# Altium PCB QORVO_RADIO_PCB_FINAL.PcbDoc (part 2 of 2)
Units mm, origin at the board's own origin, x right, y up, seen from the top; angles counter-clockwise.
Board outline 125 x 75 mm, 6 copper layers (Top Layer (RF), Int1 (GND), Int2 (5V+3.3V), Int3 (Controls), Int4 (GND), Bottom Layer (RF)), stack 1.538 mm thick; 307 components, 160 nets, 820 pads, 887 vias.
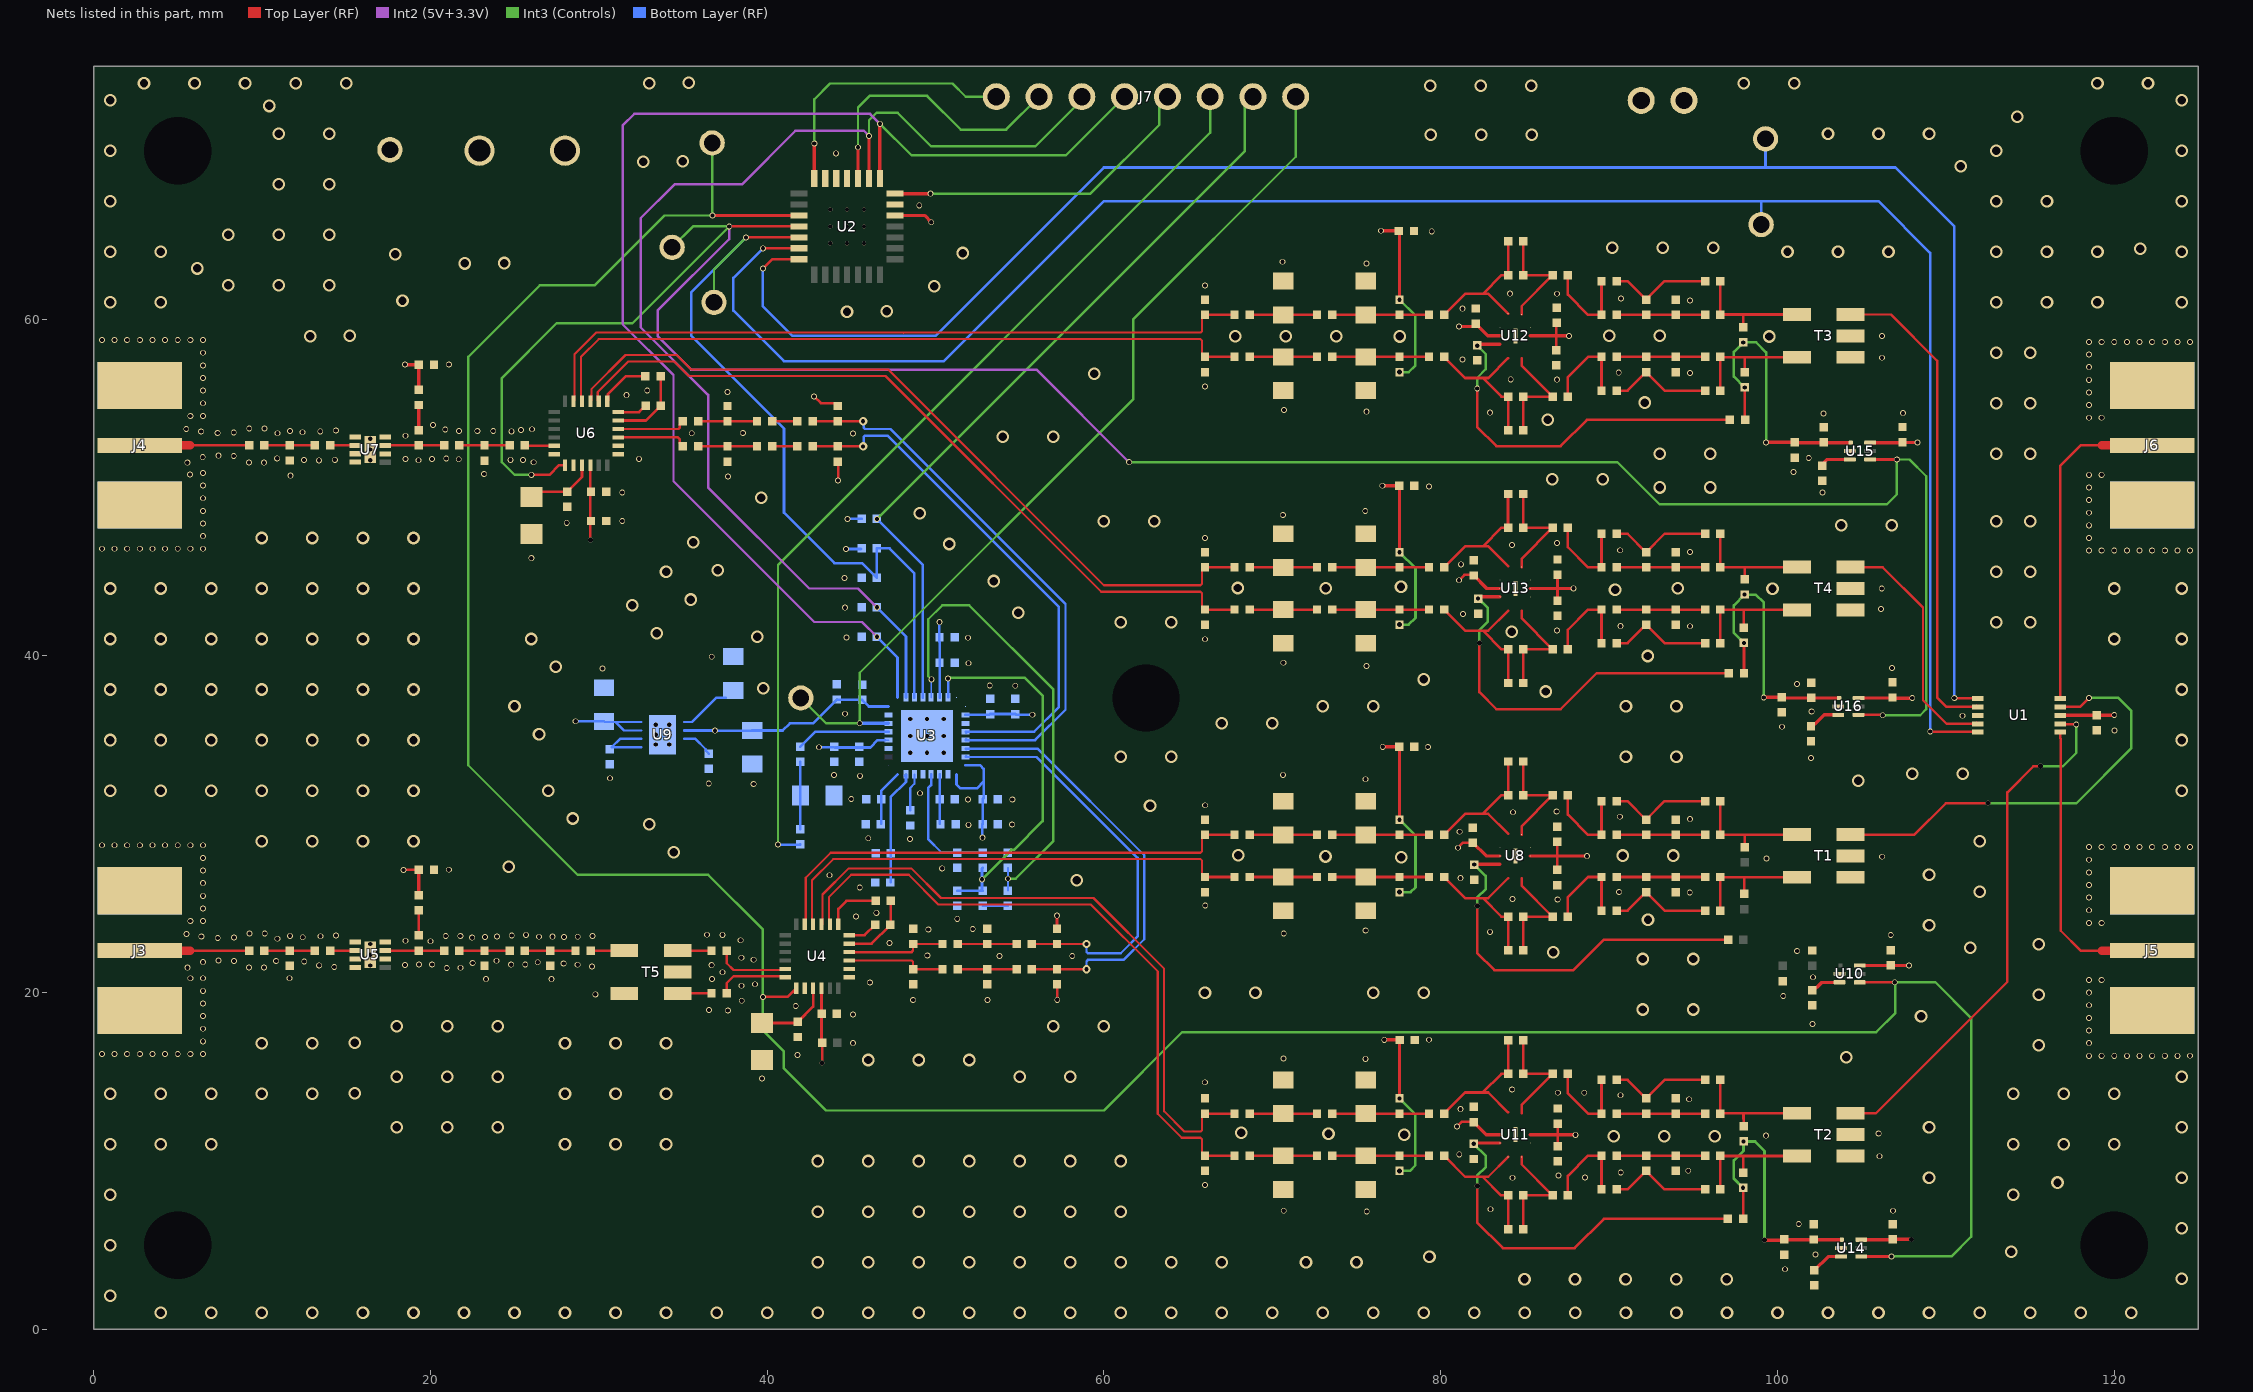
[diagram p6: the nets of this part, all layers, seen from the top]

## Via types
v1: diameter 0.35, hole 0.25, Top Layer (RF) to Bottom Layer (RF), 474 vias
v2: diameter 0.75, hole 0.5, Top Layer (RF) to Bottom Layer (RF), 365 vias
v3: diameter 0.254, hole 0.254, Top Layer (RF) to Bottom Layer (RF), tented bottom, 15 vias
v4: diameter 0.3, hole 0.3, Top Layer (RF) to Bottom Layer (RF), 14 vias
v5: diameter 0.254, hole 0.254, Top Layer (RF) to Bottom Layer (RF), tented top, 9 vias
v6: diameter 0.254, hole 0.254, Top Layer (RF) to Bottom Layer (RF), 4 vias
v7: diameter 0.5, hole 0.25, Top Layer (RF) to Bottom Layer (RF), 4 vias
v8: diameter 0.254/0.254/0.254/0.254/0.254/0.254 (per signal layer), hole 0.254, Top Layer (RF) to Bottom Layer (RF), tented top, 2 vias

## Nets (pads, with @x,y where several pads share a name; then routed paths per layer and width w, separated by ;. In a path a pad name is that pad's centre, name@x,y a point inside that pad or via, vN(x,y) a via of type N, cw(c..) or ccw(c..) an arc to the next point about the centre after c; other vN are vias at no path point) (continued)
"0.9V REG OUT_2": C118.2 C139.1 R50.2 R51.2 R56.2 U14.1 | length 16.3
  Top Layer (RF) w0.152: R56.2@97.958,6.57 R50.2@97.958,8.4
  Top Layer (RF) w0.156: C118.2@100.375,5.308 C118.2@100.411,5.344
  Top Layer (RF) w0.2: v4(99.23,5.308) C118.2@100.375,5.308 ; C118.2@100.563,5.33 U14.1@103.823,5.33
  Int3 (Controls) w0.156: v1(97.949,8.409) 97.409,8.949 97.409,10.033 97.98,10.604 v1(97.98,11.159) 98.67,11.159 99.23,10.599 v4(99.23,5.308)
"0.9V REG OUT_3": C127.2 C142.1 R63.2 R64.2 R69.2 U15.1 | length 17
  Top Layer (RF) w0.152: R69.2@98.053,54.041 v1(98.053,55.942)
  Top Layer (RF) w0.2: v1(99.323,52.676) 99.324,52.675 101.019,52.675 C127.2@101.02,52.676 ; C127.2@101.035,52.662 102.75,52.662 U15.1@104.351,52.662
  Int3 (Controls) w0.15: v1(98.053,55.942) 97.409,56.586 97.409,58.052 v1(97.971,58.614) 98.739,58.614 99.33,58.023 v1@99.33,52.683
"0.9V REG OUT_4": C136.2 C145.1 R76.2 R77.2 R82.2 U16.1 | length 16.6
  Top Layer (RF) w0.152: R82.2@98.01,38.968 v1(98.011,40.764)
  Top Layer (RF) w0.156: R82.2@98.01,38.968 R82.2@98.01,38.968
  Top Layer (RF) w0.2: v1@99.196,37.542 C136.2@100.259,37.542 ; C136.2@100.305,37.495 U16.1@103.663,37.495
  Int3 (Controls) w0.156: v1(98.011,40.764) 97.409,41.366 97.409,42.999 v1(98.048,43.638) 98.704,43.638 99.185,43.156 v1(99.185,37.531)
AVDD: C13.2 C14.2 C15.2 C16.2 C23.2 C24.2 C25.2 C26.2 C39.2 C40.2 C85.2 R9.2 R10.2 R83.2 R84.2 R85.2 R86.2 U3.6 U3.10 U3.16 U3.17 U3.28 U3.32 U9.2 | length 39.5
  Top Layer (RF) w0.156: v1(42.79,55.408) 43.189,55.009 44.028,55.009 R85.2@44.2,54.837 ; v1(44.217,50.413) R86.2@44.217,51.521 ; R83.2@57.213,23.793 v1(57.213,24.571) ; v1(57.231,19.574) R84.2@57.231,20.475
  Bottom Layer (RF) w0.1: U3.28@47.009,34.994 U3.28@47.209,34.994
  Bottom Layer (RF) w0.156: U9.2@35.07,35.57 v1@36.889,35.57 ; v1(36.903,35.556) 39.106,35.556 C85.2@39.12,35.569 40.929,35.569 41.351,35.992 42.732,35.992 C16.2@44.148,37.407 ; v1(43.082,34.569) C13.2@43.939,34.569 ; C13.2@44.03,34.558 46.13,34.558 46.566,34.994 U3.28@47.009,34.994 ; C16.2@44.169,37.386 C15.2@45.648,37.386 46.04,36.994 U3.32@47.209,36.994 ; v1(44.693,46.342) R10.2@45.58,46.342 ; v1(44.782,48.134) R9.2@45.614,48.134 ; 50.231,40.838 v1(50.231,41.999) ; U3.6@50.245,37.53 50.245,40.838 ; U3.17@51.245,32.958 51.245,32.367 51.467,32.145 52.483,32.145 52.864,32.526 ; U3.16@51.781,33.494 52.658,33.494 52.864,33.288 52.864,32.526 ; U3.10@51.781,36.494 C40.2@53.195,36.494 ; v1(52.784,29.203) C26.2@52.784,29.982 ; C26.2@52.795,29.993 C25.2@52.795,31.493 52.864,31.562 52.864,32.526 ; C40.2@53.245,36.544 C39.2@54.745,36.544 ; C39.2@54.789,36.5 v1(55.75,36.5)
CHIP_EN: J7.7 R9.1 U3.4 | length 46.1
  Int3 (Controls) w0.142: v1@46.574,48.13 v1(46.518,48.13) 68.372,69.985 68.372,72.727 J7.7@68.85,73.205
  Bottom Layer (RF) w0.156: v1(46.518,48.13) 49.245,45.403 U3.4@49.245,37.53
CPOUT: C10.2 C12.1 R5.1 U3.7 | length 22.5
  Int3 (Controls) w0.142: v1(50.737,38.653) 50.777,38.692 55.308,38.692 56.361,37.639 56.361,30.185 54.652,28.476 54.509,28.476 v1(52.761,26.728)
  Bottom Layer (RF) w0.15: U3.7@50.745,37.53 v1@50.745,38.645 ; C10.2@51.295,26.056 52.056,26.056 ; 52.089,26.056 C12.1@52.795,26.056 52.761,26.09 v1(52.761,26.728) 52.761,27.371 R5.1@52.795,27.406
CS: J7.5 U2.7 | length 19.2
  Top Layer (RF) w0.2: U2.7@47.6,67.45 v1@49.7,67.45
  Int3 (Controls) w0.142: v1(49.705,67.446) 59.196,67.446 63.292,71.542 63.292,72.727 J7.5@63.77,73.205
GND: C1.1 C2.2 C3.2 C4.2 C5.1 C6.1 C7.1 C10.1 C11.1 C13.1 C14.1 C15.1 C16.1 C17.2 C18.2 C19.2 C20.2 C21.2 C22.2 C23.1 C24.1 C25.1 C26.1 C27.2 C29.2 C34.1 C38.1 C39.1 C40.1 C49.1 C50.1 C52.2 C55.1 C57.1 C67.1 C68.1 C69.1 C70.2 C73.1 C75.2 C76.2 C77.1 C78.1 C79.1 C80.1 C82.1 C83.2 C84.2 C85.1 C86.1 C87.1 C88.2 C89.2 C90.1 C91.1 C92.2 C93.2 C94.2 C95.1 C96.1 C97.1 C98.1 C99.2 C100.2 C101.2 C102.1 C103.1 C104.1 C105.1 C106.2 C107.2 C108.2 C109.1 C110.1 C111.1 C113.2 C114.2 C115.1 C116.1 C117.1 C118.1 C120.1 C122.2 C123.2 C124.1 C125.1 C126.1 C127.1 C129.1 C131.2 C132.2 C133.1 C134.1 C135.1 C136.1 C138.1 C139.2 C140.2 C141.1 C142.2 C143.2 C144.1 C145.2 C146.2 C147.1 C148.2 C149.2 C150.1 J1.2 J2.1 J2.2 J3.1 J3.3 J3.4 J3.5 J4.1 J4.3 J4.4 J4.5 J5.1 J5.3 J5.4 J5.5 J6.1 J6.3 J6.4 J6.5 R6.2 R8.2 R11.2 R12.1 R13.1 R14.1 R15.1 R16.1 R17.1 R18.1 T1.2 T1.3 T2.2 T2.3 T3.2 T3.3 T4.2 T4.3 T5.2 T5.4 U1.3 U2.6 U2.11 U2.12 U2.13 U2.29 U3.8 U3.9 U3.11 U3.18 U3.21 U3.27 U3.31 U3.33 U4.8 U4.13 U4.14 U4.25 U5.1 U5.3 U5.4 U5.6 U5.8 U5.9 U6.6 U6.8 U6.13 U6.14 U6.25 U7.1 U7.3 U7.4 U7.6 U7.8 U7.9 U8.8 U8.10 U8.11 U9.4 U9.9 U10.2 U11.8 U11.10 U11.11 U12.8 U12.10 U12.11 U13.8 U13.10 U13.11 U14.2 U15.2 U16.2
  other v1: 100.45,3.572 102.254,4.446 101.265,6.263 75.609,6.999 70.679,7.047 106.854,7.046 82.954,7.139 66.007,8.583 84.261,9.008 88.569,9.021 86.995,9.136 90.69,9.316 94.698,9.423 106.057,10.284 81.1,10.4 99.324,11.508 106.007,11.631 81.174,13.081 94.754,13.671 90.672,13.905 86.955,14.053 88.525,14.057 84.245,14.242 65.993,14.676 39.7,14.9 70.658,16.084 75.534,16.07 118.5,16.25 119.25,16.25 120,16.25 120.75,16.25 121.5,16.25 122.25,16.25 123,16.25 123.75,16.25 124.5,16.25 41.8,16.3 0.5,16.358 1.25,16.358 2,16.358 2.75,16.358 3.5,16.358 4.25,16.358 5,16.358 5.75,16.358 6.5,16.358 45.1,17 118.5,17 6.5,17.108 79.3,17.2 118.5,17.75 6.5,17.858 102.086,18.143 118.5,18.5 6.5,18.608 45.1,18.7 37.667,18.946 36.556,18.973 41.7,19.2 118.5,19.25 6.5,19.358 38.496,19.518 48.675,19.562 53.08,19.556 100.34,19.804 29.8,19.9 118.5,20 6.5,20.108 38.474,20.41 39.282,20.499 46.1,20.6 118.5,20.75 119.25,20.75 23.3,20.8 27.2,20.8 36.725,20.816 5.75,20.858 6.5,20.858 11.633,20.853 102.115,20.912 37.348,21.209 20.975,21.465 5.58,21.484 10.132,21.485 21.788,21.481 9.242,21.501 14.295,21.524 29.603,21.556 13.401,21.624 18.492,21.638 36.707,21.632 19.335,21.674 20.112,21.679 24.802,21.662 25.641,21.669 28.752,21.659 27.921,21.73 22.517,21.768 26.379,21.804 6.497,21.81 12.518,21.85 10.848,21.881 7.426,21.902 8.338,21.888 23.931,21.893 39.202,21.952 38.47,22.073 53.806,22.177 58.124,22.184 49.515,22.199 101.168,22.475 47.274,22.95 20.013,23.052 18.531,23.079 38.429,23.113 10.916,23.202 7.381,23.252 8.336,23.271 22.488,23.264 12.423,23.292 23.253,23.304 27.934,23.299 26.462,23.321 27.248,23.325 28.756,23.321 6.403,23.336 13.474,23.347 23.965,23.331 11.668,23.373 20.92,23.362 21.783,23.372 29.638,23.364 14.4,23.4 24.838,23.389 106.722,23.419 25.691,23.434 36.431,23.439 37.354,23.435 5.515,23.482 9.26,23.51 10.168,23.513 70.678,23.519 82.92,23.611 75.545,23.69 49.573,23.745 52.21,23.784 118.5,24.142 119.25,24.142 5.75,24.25 6.5,24.25 51.291,24.383 45.278,24.524 46.487,24.74 118.5,24.892 6.5,25 66.015,25.181 86.945,25.533 84.257,25.563 118.5,25.642 6.5,25.75 90.598,25.97 94.79,25.951 45.5,26.25 118.5,26.392 6.5,26.5 81.183,26.797 43.709,26.969 118.5,27.142 6.5,27.25 21.1,27.3 50.395,27.383 118.5,27.892 99.34,27.973 6.5,28 106.217,28.068 118.5,28.642 119.25,28.642 120,28.642 120.75,28.642 121.5,28.642 122.25,28.642 123,28.642 123.75,28.642 124.5,28.642 0.5,28.75 1.25,28.75 2,28.75 2.75,28.75 3.5,28.75 4.25,28.75 5,28.75 5.75,28.75 6.5,28.75 48.492,29.121 46.009,29.166 81.126,29.554 51.958,29.966 54.552,29.978 94.806,30.303 90.638,30.443 84.286,30.715 86.888,30.752 66.013,31.126 51.938,31.467 54.563,31.475 45,31.5 49.087,31.843 39.204,32.395 36.537,32.422 75.534,32.672 30.676,32.734 45.519,32.876 43.97,32.929 70.638,32.936 101.991,33.937 79.234,34.596 120.019,35.561 100.269,35.79 110.983,36.444 44.628,36.559 102.029,36.696 53.22,38.234 54.735,38.226 101.166,38.334 30.228,39.243 106.795,39.286 75.598,39.393 51.957,39.56 70.656,39.593 36.715,39.948 66.008,40.984 51.933,41.075 44.715,41.09 86.9,41.5 90.674,41.762 94.803,41.759 81.318,42.485 106.148,42.781 44.632,42.861 106.189,43.995 44.589,44.626 81.207,45.436 26,45.8 94.803,46.172 118.5,46.25 119.25,46.25 120,46.25 120.75,46.25 121.5,46.25 122.25,46.25 123,46.25 123.75,46.25 124.5,46.25 90.657,46.272 0.5,46.358 1.25,46.358 2,46.358 2.75,46.358 3.5,46.358 4.25,46.358 5,46.358 5.75,46.358 6.5,46.358 84.23,46.582 86.9,46.7 66.002,46.998 118.5,47 6.5,47.108 118.5,47.75 6.5,47.858 28.1,47.9 31.4,48 70.625,48.358 118.5,48.5 6.5,48.608 75.516,48.608 118.5,49.25 6.5,49.358 31.4,49.7 102.68,49.702 118.5,50 79.31,50.049 6.5,50.108 37.671,50.656 11.7,50.7 118.5,50.75 119.25,50.75 5.728,50.769 23.2,50.8 6.5,50.858 100.955,50.911 5.572,51.471 10.123,51.471 9.233,51.488 26.14,51.497 13.392,51.61 19.303,51.615 12.505,51.628 14.33,51.64 24.766,51.641 25.508,51.636 21.691,51.671 18.524,51.684 20.109,51.693 32.4,51.7 20.949,51.723 10.907,51.73 101.856,51.742 6.488,51.797 8.329,51.874 7.417,51.888 18.532,53.067 10.921,53.215 35.522,53.215 45.102,53.211 7.372,53.239 38.558,53.23 8.327,53.257 12.415,53.279 6.395,53.322 11.664,53.353 13.465,53.333 21.703,53.352 24.819,53.331 22.794,53.361 23.737,53.356 14.391,53.386 25.379,53.404 20.885,53.438 5.507,53.469 26.043,53.455 9.252,53.496 10.16,53.499 20.165,53.705 118.5,54.142 119.25,54.142 5.75,54.25 6.5,54.25 102.738,54.386 107.455,54.411 82.936,54.44 75.6,54.5 70.7,54.6 118.5,54.892 6.5,55 31.645,55.479 118.5,55.642 37.657,55.673 6.5,55.75 32.885,55.753 66,56 86.9,56.4 118.5,56.392 84.157,56.42 6.5,56.5 94.8,56.8 90.575,56.817 118.5,57.142 6.5,57.25 21.1,57.3 81.3,57.6 106.2,57.7 118.5,57.892 6.5,58 118.5,58.642 119.25,58.642 120,58.642 120.75,58.642 121.5,58.642 122.25,58.642 123,58.642 123.75,58.642 124.5,58.642 0.5,58.75 1.25,58.75 2,58.75 2.75,58.75 3.5,58.75 4.25,58.75 5,58.75 5.75,58.75 6.5,58.75 106.2,59 81.301,60.616 94.8,61.1 90.701,61.221 86.9,61.5 84.115,61.506 66,62 75.6,63.3 70.6,63.4 79.471,65.209 49.037,66.753 44.095,69.842
  other v2: 4,1 7,1 10,1 13,1 16,1 19,1 22,1 25,1 28,1 31,1 34,1 37,1 40,1 43,1 46,1 49,1 52,1 55,1 58,1 61,1 64,1 67,1 70,1 73,1 76,1 79,1 82,1 85,1 88,1 91,1 94,1 97,1 100,1 103,1 106,1 109,1 112,1 115,1 118,1 121,1 1,2 84.977,2.977 87.977,2.977 90.977,2.977 93.977,2.977 96.977,2.977 124,3 43,4 46,4 49,4 52,4 55,4 58,4 61,4 64,4 67,4 72,4 75,4 79.332,4.315 113.887,4.61 1,5 124,6 43,7 46,7 49,7 52,7 55,7 58,7 61,7 1,8 114,8 116.629,8.723 109,9 124,9 43,10 46,10 49,10 52,10 55,10 58,10 61,10 1,11 4,11 7,11 28,11 31,11 34,11 114,11 117,11 120,11 90.267,11.468 93.267,11.468 96.267,11.468 77.838,11.558 73.34,11.614 68.159,11.683 18,12 21,12 24,12 109,12 124,12 1,14 4,14 7,14 10,14 13,14 28,14 31,14 34,14 114,14 117,14 120,14 15.517,14.023 18,15 21,15 24,15 55,15 58,15 124,15 46,16 49,16 52,16 104.089,16.165 115.524,16.884 10,17 13,17 28,17 31,17 34,17 15.517,17.023 18,18 21,18 24,18 57,18 60,18 108.524,18.605 92,19 95,19 115.524,19.884 66,20 69,20 76,20 79,20 92,22 95,22 86.683,22.395 111.454,22.658 115.524,22.884 109,24 92.311,24.325 112,26 58.397,26.681 109,27 24.657,27.468 77.658,28.031 73.16,28.088 67.979,28.156 90.808,28.141 93.808,28.141 34.457,28.344 10,29 13,29 16,29 19,29 112,29 33,30 28.457,30.344 62.74,31.109 1,32 4,32 7,32 10,32 13,32 16,32 19,32 27,32 124,32 104.788,32.589 108,33 111,33 61,34 64,34 91,34 94,34 1,35 4,35 7,35 10,35 13,35 16,35 19,35 124,35 26.457,35.344 67,36 70,36 25,37 73,37 76,37 91,37 94,37 86.237,37.884 1,38 4,38 7,38 10,38 13,38 16,38 19,38 124,38 39.762,38.066 79,38.599 27.457,39.344 92.295,39.989 1,41 4,41 7,41 10,41 13,41 16,41 19,41 26,41 120,41 124,41 39.42,41.128 33.457,41.344 84.216,41.433 61,42 64,42 113,42 115,42 54.91,42.569 32,43 35.457,43.344 90.353,43.931 99.702,43.979 1,44 4,44 7,44 10,44 13,44 16,44 19,44 120,44 124,44 67.941,44.029 73.183,44.013 94.075,44.013 77.644,44.111 53.451,44.442 34,45 113,45 115,45 37.063,45.093 50.821,46.64 35.605,46.749 10,47 13,47 16,47 19,47 103.783,47.756 106.783,47.756 60,48 63,48 113,48 115,48 49.056,48.477 39.654,49.395 93,50 96,50 86.627,50.481 89.627,50.481 93,52 96,52 113,52 115,52 54,53 57,53 86.35,54.021 113,55 115,55 92.118,55.042 59.427,56.75 113,58 115,58 99.501,58.962 12.871,58.987 67.808,58.989 70.808,58.989 73.808,58.989 77.575,58.967 15.227,59.009 90,59 93,59 44.747,60.435 47.103,60.458 1,61 4,61 113,61 116,61 119,61 124,61 18.35,61.084 49.924,61.943 8,62 11,62 14,62 6.164,63.005 22.042,63.302 24.398,63.325 17.93,63.852 51.609,63.919 100.593,63.994 103.593,63.994 106.593,63.994 1,64 4,64 113,64 116,64 119,64 124,64 121.55,64.185 90.19,64.224 93.19,64.224 96.19,64.224 8,65 11,65 14,65 1,67 113,67 116,67 124,67 11,68 14,68 110.886,69.068 32.646,69.337 35.002,69.36 1,70 113,70 124,70 79.399,70.95 82.399,70.95 85.399,70.95 11,71 14,71 103,71 106,71 109,71 114.236,72.006 10.443,72.654 1,73 124,73 79.373,73.855 82.373,73.855 85.373,73.855 3,74 6,74 9,74 12,74 15,74 33,74 98,74 101,74 119,74 122,74 35.356,74.022
  other v3: 48.495,34.244 49.495,34.244 50.495,34.244 33.395,34.735 34.195,34.735 48.495,35.244 49.495,35.244 50.495,35.244 33.395,35.32 34.195,35.32 33.395,35.905 34.195,35.905 48.495,36.244 49.495,36.244 50.495,36.244
  other v5: 43.75,64.5 44.75,64.5 45.75,64.5 43.75,65.5 44.75,65.5 45.75,65.5 43.75,66.5 44.75,66.5 45.75,66.5
  other v6: 16.435,21.61 16.435,22.25 16.435,51.61 16.435,52.25
  other v8: 16.435,22.89 16.435,52.89
"HE LNA OUTPUT": C72.2 U6.5 | length 1.7
  Top Layer (RF) w0.143: C72.2@25.643,52.473 U6.5@27.355,52.473
"HEM EN": HEMEN.1 U2.18 U6.7 U15.4 U16.4 | length 144.6
  Top Layer (RF) w0.157: v1(26,50.75) 27.072,50.75 27.645,51.323 U6.7@28.005,51.323 ; v1(37.75,65.5) U2.18@41.9,65.5 ; U16.4@104.813,36.495 v1@106.23,36.495 ; U15.4@105.501,51.662 v1@107.082,51.662
  Int2 (5V+3.3V) w0.142: v1(37.75,65.5) 37.75,64.75 33.5,60.5 33.5,59 35.5,57 56,57 v1(61.5,51.5)
  Int3 (Controls) w0.142: v1(26,50.75) 25,50.75 24.25,51.5 24.25,56.5 27.5,59.75 32,59.75 v1(37.75,65.5) 35.602,65.5 HEMEN.1@34.361,64.259 ; v1(61.5,51.5) 90.5,51.5 93,49 106.5,49 107.085,49.585 v1(107.085,51.659) 107.841,51.659 108.835,50.665 108.835,36.835 108.475,36.475 v1(106.251,36.475)
"I HE CH": T3.1 U1.2 | length 29
  Top Layer (RF) w0.143: T3.1@104.34,60.27 106.73,60.27 109.476,57.524 109.476,37.524 110.034,36.966 U1.2@111.895,36.966 U1.2@111.817,37.044
"I LE CH": T1.1 U1.9 | length 25.8
  Top Layer (RF) w0.143: T1.1@104.34,29.388 108.138,29.388 110,31.25 v4(112.5,31.25) ; U1.9@116.795,36.966 117.966,36.966 v1(118.5,37.5)
  Int3 (Controls) w0.142: v4(112.5,31.25) 117.75,31.25 121,34.5 121,36.75 120.25,37.5 v1(118.5,37.5)
I/O_I: SWI.1 U1.1 U2.21 | length 112.8
  Top Layer (RF) w0.157: v1(39.75,63) 40.3,63.55 U2.21@41.9,63.55 ; v1@110.517,37.483 111.878,37.483 U1.1@111.895,37.466
  Bottom Layer (RF) w0.157: v1(39.75,63) 39.75,60.75 41.5,59 50,59 60,69 107,69 110.487,65.513 110.487,37.513 v1(110.5,37.5) ; 99.291,69.002 SWI.1@99.291,70.703
I/O_Q: SWQ.1 U1.5 U2.20 | length 116.7
  Top Layer (RF) w0.157: v1(39.75,64.2) U2.20@41.9,64.2 ; v1@109.09,35.487 111.874,35.487 U1.5@111.895,35.466
  Bottom Layer (RF) w0.157: v1(39.75,64.2) 38,62.45 38,60.5 41,57.5 50.5,57.5 60,67 106,67 109.068,63.932 v1(109.068,35.509) ; SWQ.1@99.033,65.608 99.033,66.967
I_HE_AA_N: L41.2 R60.2 R64.1 T3.6 | length 7.3
  Top Layer (RF) w0.152: L41.2@96.6,60.27 R60.2@96.6,62.25 ; L41.2@96.62,60.27 T3.6@101.16,60.27 ; R64.1@97.971,59.514 97.971,60.263
I_HE_AA_P: L43.2 R63.1 R67.2 T3.4 | length 7.4
  Top Layer (RF) w0.152: R67.2@96.6,55.75 L43.2@96.6,57.73 ; L43.2@96.62,57.73 T3.4@101.16,57.73 ; R63.1@98.044,56.838 98.044,57.727
I_HE_LPF_INPUT_N: C102.2 L30.1 U6.22 | length 42.8
  Top Layer (RF) w0.128: U6.22@28.946,55.182 28.946,57.755 30,58.809 47.942,58.809 65.742,58.809 65.819,58.731 C102.2@65.819,57.934
  Top Layer (RF) w0.133: U6.22@28.946,55.182 U6.22@29.005,55.123 ; C102.2@65.819,57.934 C102.2@66.003,57.75
  Top Layer (RF) w0.152: C102.2@66.003,57.75 L30.1@67.753,57.75
I_HE_LPF_INPUT_P: C99.1 L28.1 U6.23 | length 43.4
  Top Layer (RF) w0.128: 28.564,55.484 28.564,57.914 29.842,59.191 48.101,59.191 65.742,59.191 65.819,59.269 C99.1@65.819,60.066
  Top Layer (RF) w0.133: U6.23@28.505,55.123 28.564,55.182 28.564,55.484 ; C99.1@65.819,60.066 C99.1@66.003,60.25
  Top Layer (RF) w0.152: C99.1@66.003,60.25 L28.1@67.753,60.25
I_HE_LPF_OUTPUT_N: C128.1 R39.2 R68.1 U12.6 | length 8.8
  Top Layer (RF) w0.152: R39.2@80.203,57.75 81.453,56.5 82.5,56.5 ; C128.1@84,53.39 R68.1@84,55.39 83.61,55.39 82.5,56.5 ; U12.6@84,57.675 82.825,56.5 82.5,56.5
I_HE_LPF_OUTPUT_P: C121.1 R38.2 R57.1 U12.2 | length 8.8
  Top Layer (RF) w0.152: R38.2@80.203,60.25 81.453,61.5 82.825,61.5 U12.2@84,60.325 ; 82.5,61.5 83.61,62.61 R57.1@84,62.61 C121.1@84,64.61
I_LE_AA_N: L21.2 R22.2 R26.1 T1.6 | length 7.3
  Top Layer (RF) w0.152: L21.2@96.6,29.388 R22.2@96.6,31.368 ; L21.2@96.62,29.388 T1.6@101.16,29.388 ; R26.1@98.053,28.643 98.053,29.379
I_LE_AA_P: L23.2 R25.1 R29.2 T1.4 | length 7.5
  Top Layer (RF) w0.152: R29.2@96.6,24.868 L23.2@96.6,26.848 ; L23.2@96.62,26.848 T1.4@101.16,26.848 ; R25.1@98.021,25.863 98.021,26.825
I_LE_LPF_INPUT_N: C95.2 L26.1 U4.22 | length 29.1
  Top Layer (RF) w0.128: U4.22@42.731,24.059 42.67,24.12 42.67,26.67 43.929,27.929 60.441,27.929 65.742,27.929 65.817,27.854 65.817,27.054 C95.2@66.003,26.868
  Top Layer (RF) w0.152: C95.2@66.003,26.868 L26.1@67.753,26.868
I_LE_LPF_INPUT_P: C92.1 L24.1 U4.23 | length 29.9
  Top Layer (RF) w0.128: U4.23@42.231,24.059 42.292,24.059 42.292,26.826 43.773,28.307 60.597,28.307 65.742,28.307 65.817,28.382 65.817,29.182 C92.1@66.003,29.368
  Top Layer (RF) w0.15: U4.23@42.231,24.059 U4.23@42.281,24.109
  Top Layer (RF) w0.152: C92.1@66.003,29.368 L24.1@67.753,29.368
I_LE_LPF_OUTPUT_N: C81.1 R30.1 R35.2 U8.6 | length 8.8
  Top Layer (RF) w0.152: R35.2@80.203,26.868 81.453,25.618 82.499,25.618 ; 83.609,24.508 82.499,25.618 ; C81.1@84,22.508 R30.1@84,24.5 ; U8.6@84,26.793 82.825,25.618 82.499,25.618
  Top Layer (RF) w0.156: 83.609,24.508 R30.1@84,24.508
I_LE_LPF_OUTPUT_P: C74.1 R19.1 R34.2 U8.2 | length 8.8
  Top Layer (RF) w0.133: 83.61,31.728 R19.1@84,31.728
  Top Layer (RF) w0.152: R34.2@80.203,29.368 81.453,30.618 82.5,30.618 82.825,30.618 U8.2@84,29.443 ; 82.495,30.615 83.605,31.725 ; R19.1@84,31.728 C74.1@84,33.728
"LE_LNA OUTPUT_N": C58.2 U4.6 | length 4.5
  Top Layer (RF) w0.128: C58.2@37.6,19.956 37.6,20.57 38,20.97 41.02,20.97 U4.6@41.081,20.909
  Top Layer (RF) w0.143: C58.2@37.6,19.956 C58.2@37.778,20.135
"LE_LNA OUTPUT_P": C56.1 U4.5 | length 4.7
  Top Layer (RF) w0.128: C56.1@37.6,22.496 37.6,21.748 38,21.348 41.02,21.348 U4.5@41.081,21.409
  Top Layer (RF) w0.143: C56.1@37.6,22.496 C56.1@37.778,22.317
LEL-10: C54.2 C57.2 L17.1 | length 3
  Top Layer (RF) w0.143: C54.2@25.62,22.496 C57.2@27.12,22.496 ; C57.2@27.12,22.496 L17.1@28.62,22.496
"LEM EN": LEMEN.1 U2.17 U4.7 U10.4 U14.4 | length 182.9
  Top Layer (RF) w0.157: v1(36.75,66.15) U2.17@41.9,66.15 ; v1(39.75,19.75) 41.222,19.75 U4.7@41.731,20.259 ; U10.4@104.884,20.614 v1@106.959,20.614 ; U14.4@104.973,4.33 v1@106.769,4.33
  Int3 (Controls) w0.142: LEMEN.1@36.745,70.455 36.745,66.155 v1(36.75,66.15) 33.9,66.15 29.75,62 26.5,62 22.25,57.75 22.25,33.5 28.75,27 36.5,27 39.75,23.75 v1(39.75,19.75) 39.75,17.75 41,16.5 41,15.5 43.5,13 60,13 64.646,17.646 105.854,17.646 107,18.793 107,20.58 v1(106.963,20.618) 109.382,20.618 111.5,18.5 111.5,5.5 110.338,4.338 v1(106.777,4.338)
LO_12_N: C33.1 R85.1 U3.13 | length 32.8
  Top Layer (RF) w0.143: C33.1@42.7,53.937 v7(45.7,53.937)
  Bottom Layer (RF) w0.143: v7@45.733,54.024 45.733,53.555 45.817,53.471 47.32,53.471 57.72,43.071 57.72,42.586 57.72,36.8 55.913,34.994 U3.13@51.781,34.994 U3.13@51.835,35.047
LO_12_P: C30.1 R86.1 U3.12 | length 31.5
  Top Layer (RF) w0.143: C30.1@42.7,52.438 v7(45.7,52.438)
  Bottom Layer (RF) w0.143: v7@45.733,52.525 45.733,52.994 45.817,53.078 47.157,53.078 57.327,42.909 57.327,36.963 55.858,35.494 U3.12@51.781,35.494 U3.12@51.835,35.44
LO_14_N: C36.2 R83.1 U3.15 | length 24.6
  Top Layer (RF) w0.143: C36.2@55.717,22.889 R83.1@57.217,22.889 v7(58.967,22.889)
  Bottom Layer (RF) w0.143: U3.15@51.835,34.047 U3.15@51.781,33.994 56.006,33.994 62,28 62,23.336 61,22.336 59.051,22.336 58.967,22.419 v7(58.967,22.889)
LO_14_P: C32.2 R84.1 U3.14 | length 26
  Top Layer (RF) w0.143: C32.2@55.717,21.389 R84.1@57.217,21.389 v7(58.967,21.389)
  Bottom Layer (RF) w0.143: U3.14@51.835,34.44 U3.14@51.781,34.494 56.062,34.494 62.393,28.163 62.393,23.173 61.163,21.943 59.051,21.943 58.967,21.859 v7(58.967,21.389)
LO_HE_OUT_N: L13.2 U6.16 | length 4.2
  Top Layer (RF) w0.143: U6.16@31.155,53.473 34.738,53.473 34.822,53.557 34.822,53.759 L13.2@35,53.937
LO_HE_OUT_P: L10.2 U6.15 | length 4.2
  Top Layer (RF) w0.143: U6.15@31.155,52.973 34.704,52.973 34.822,52.855 34.822,52.616 L10.2@35,52.438
LO_LE_OUT_N: C38.2 L14.2 U4.16 | length 6
  Top Layer (RF) w0.143: U4.16@44.881,22.409 48.583,22.409 48.667,22.493 C38.2@48.667,22.889 L14.2@50.417,22.889
LO_LE_OUT_P: C27.1 L11.2 U4.15 | length 6
  Top Layer (RF) w0.143: U4.15@44.881,21.909 48.591,21.909 48.667,21.833 C27.1@48.667,21.389 L11.2@50.417,21.389
LOAD_EN: LOADEN.1 R10.1 R12.2 U2.19 U3.3 | length 46.8
  Top Layer (RF) w0.157: v1(38.75,64.85) U2.19@41.9,64.85
  Int3 (Controls) w0.142: LOADEN.1@36.849,60.994 36.849,62.949 v1(38.75,64.85)
  Bottom Layer (RF) w0.156: R10.1@46.518,46.38 47.265,46.38 48.745,44.9 U3.3@48.745,37.53
  Bottom Layer (RF) w0.157: v1(38.75,64.85) 35.5,61.6 35.5,59 41,53.5 41,48.5 44,45.5 45.648,45.5 R12.2@46.518,44.63 R10.1@46.518,46.38
MISO: J7.2 U2.10 | length 16.8
  Top Layer (RF) w0.2: U2.10@45.4,68.35 v1@45.4,70.126
  Int3 (Controls) w0.142: v1(45.396,70.204) 45.396,72.56 46.086,73.25 49.5,73.25 51.5,71.25 54.195,71.25 J7.2@56.15,73.205
MOSI: J7.3 R13.2 U2.9 U3.2 | length 70.9
  Top Layer (RF) w0.2: U2.9@46.05,68.35 v1@46.05,70.814
  Int2 (5V+3.3V) w0.142: v1(46.053,70.873) 45.745,71.18 41.68,71.18 38.5,68 34.5,68 32.5,66 32.5,59.5 36.5,55.5 36.5,50 42.5,44 45.398,44 v1(46.518,42.88)
  Int3 (Controls) w0.142: v1(46.053,70.873) 46.053,71.803 46.5,72.25 47.75,72.25 49.75,70.25 55.921,70.25 58.69,73.019 J7.3@58.69,73.205
  Bottom Layer (RF) w0.156: v1(46.518,42.88) 48.245,41.153 U3.2@48.245,37.53
MUX_OUT: J7.8 MUXOUT.1 U3.30 | length 54.4
  Int3 (Controls) w0.142: MUXOUT.1@42,37.5 43.5,36 v1(45.5,36) 45.5,39 61.75,55.25 61.75,60 71.39,69.64 J7.8@71.39,73.205 J7.8@70.912,72.727
  Bottom Layer (RF) w0.2: v1@45.506,35.994 U3.30@47.209,35.994
NetC3_1: C3.1 L1.2 L2.1 | length 4
  Top Layer (RF) w0.152: L1.2@68.653,12.819 C3.1@70.653,12.819 L2.1@72.653,12.819
NetC4_1: C4.1 L2.2 R2.1 R3.1 | length 5.8
  Top Layer (RF) w0.152: L2.2@73.553,12.819 C4.1@75.553,12.819 R3.1@79.303,12.819
NetC6_2: C6.2 L3.2 L4.1 | length 4
  Top Layer (RF) w0.152: L3.2@68.653,10.319 L4.1@72.653,10.319
NetC7_2: C7.2 L4.2 R1.2 R4.1 | length 5.8
  Top Layer (RF) w0.152: L4.2@73.553,10.319 C7.2@75.553,10.319 R1.2@77.553,10.319 R4.1@79.303,10.319
NetC8_1: C8.1 U3.29 | length 5.6
  Bottom Layer (RF) w0.156: C8.1@41.978,34.609 42.863,35.494 U3.29@47.209,35.494
NetC8_2: C8.2 C9.1 R6.1 | length 4
  Bottom Layer (RF) w0.157: C9.1@41.978,29.709 R6.1@41.978,31.709 C8.2@41.978,33.709
NetC12_2: C12.2 R7.2 | length 1.5
  Bottom Layer (RF) w0.15: C12.2@52.795,25.156 R7.2@54.295,25.156
NetC17_1: C17.1 C18.1 U3.24 | length 3.3
  Bottom Layer (RF) w0.156: C18.1@46.786,30.02 C17.1@46.786,31.493 46.786,31.999 U3.24@47.745,32.958
NetC19_1: C19.1 C21.1 U3.23 | length 6.9
  Bottom Layer (RF) w0.156: C21.1@47.342,26.56 C19.1@47.342,28.268 47.342,31.605 48.245,32.508 U3.23@48.245,32.958 U3.23@48.173,32.886
NetC20_1: C20.1 C22.1 U3.19 | length 2.9
  Bottom Layer (RF) w0.156: C22.1@50.245,31.499 U3.19@50.245,32.958 ; C20.1@50.251,30.039 C22.1@50.251,31.493
NetC29_1: C29.1 L9.2 L10.1 | length 3.5
  Top Layer (RF) w0.143: L10.1@35.9,52.438 C29.1@37.65,52.438 L9.2@39.4,52.438
NetC30_2: C30.2 L9.1 | length 1.5
  Top Layer (RF) w0.143: L9.1@40.3,52.438 C30.2@41.8,52.438
NetC32_1: C32.1 C148.1 L11.1 | length 3.5
  Top Layer (RF) w0.143: L11.1@51.317,21.389 C148.1@53.067,21.389 C32.1@54.817,21.389
NetC33_2: C33.2 L12.1 | length 1.5
  Top Layer (RF) w0.143: L12.1@40.3,53.937 C33.2@41.8,53.937
NetC34_2: C34.2 L12.2 L13.1 | length 3.5
  Top Layer (RF) w0.143: L13.1@35.9,53.937 C34.2@37.65,53.937 L12.2@39.4,53.937
NetC36_1: C36.1 C149.1 L14.1 | length 3.5
  Top Layer (RF) w0.143: L14.1@51.317,22.889 C149.1@53.067,22.889 C36.1@54.817,22.889
NetC41_1: C41.1 U4.19 | length 3.3
  Top Layer (RF) w0.156: U4.19@44.231,24.059 44.231,24.981 44.706,25.456 C41.1@46.44,25.456
NetC41_2: C41.2 C42.2 U4.17 | length 4.3
  Top Layer (RF) w0.156: U4.17@44.881,22.909 46.197,22.909 C42.2@47.315,24.027 ; C42.2@47.34,24.052 C41.2@47.34,25.456
NetC42_1: C42.1 U4.18 | length 1.8
  Top Layer (RF) w0.156: U4.18@44.881,23.409 45.797,23.409 C42.1@46.415,24.027
NetC49_2: C49.2 R15.2 U4.9 | length 4.6
  Top Layer (RF) w0.156: C49.2@39.695,18.197 41.748,18.197 R15.2@41.82,18.269 42.731,19.179 U4.9@42.731,20.259 U4.9@42.684,20.164
NetC53_1: C53.1 J3.2 | length 6.5
  Top Layer (RF) w0.143: 5.75,22.5 C53.1@9.25,22.5
  Top Layer (RF) w0.5: J3.2@2.75,22.5 5.75,22.5
NetC53_2: C53.2 L15.1 R16.2 | length 3
  Top Layer (RF) w0.143: C53.2@10.15,22.5 R16.2@11.65,22.5 L15.1@13.15,22.5
NetC54_1: C54.1 C55.2 L16.2 | length 3
  Top Layer (RF) w0.143: L16.2@21.72,22.496 C55.2@23.22,22.496 C54.1@24.72,22.496
NetC56_2: C56.2 T5.1 | length 2
  Top Layer (RF) w0.143: T5.1@34.7,22.496 C56.2@36.7,22.496
NetC58_1: C58.1 T5.3 | length 2
  Top Layer (RF) w0.143: T5.3@34.7,19.956 C58.1@36.7,19.956
NetC59_1: C59.1 U6.19 | length 3.1
  Top Layer (RF) w0.156: U6.19@30.505,55.123 30.552,55.17 30.552,55.552 31.608,56.608 C59.1@32.776,56.608
NetC59_2: C59.2 C60.2 U6.17 | length 4.6
  Top Layer (RF) w0.156: U6.17@31.155,53.973 32.8,53.973 C60.2@33.685,54.858 ; C60.2@33.676,54.858 C59.2@33.676,56.608
NetC60_1: C60.1 U6.18 | length 1.8
  Top Layer (RF) w0.156: U6.18@31.155,54.473 32.4,54.473 C60.1@32.785,54.858
NetC68_2: C68.2 R17.2 U6.9 | length 3.7
  Top Layer (RF) w0.156: C68.2@26.332,49.748 R17.2@28.134,49.748 29.005,50.619 U6.9@29.005,51.323
NetC71_1: C71.1 J4.2 | length 6.5
  Top Layer (RF) w0.143: 5.75,52.5 C71.1@9.25,52.5
  Top Layer (RF) w0.5: J4.2@2.75,52.5 5.75,52.5
NetC71_2: C71.2 L18.1 R18.2 | length 3
  Top Layer (RF) w0.143: C71.2@10.15,52.5 R18.2@11.65,52.5 ; R18.2@11.65,52.5 L18.1@13.15,52.5
NetC72_1: C72.1 C73.2 L19.2 | length 3
  Top Layer (RF) w0.143: L19.2@21.72,52.496 21.899,52.496 C73.2@23.22,52.496 24.542,52.496 C72.1@24.72,52.496
NetC74_2: C74.2 R19.2 R21.1 U8.1 | length 6.9
  Top Layer (RF) w0.152: U8.1@84.8,29.393 84.8,29.878 R21.1@86.65,31.728 R19.2@84.9,31.728 C74.2@84.9,33.728
NetC75_1: C75.1 L20.2 L21.1 R23.1 | length 5.3
  Top Layer (RF) w0.152: L20.2@90.45,29.368 R23.1@92.2,29.368 C75.1@93.95,29.368 L21.1@95.7,29.368
NetC79_2: C79.2 L22.2 L23.1 R24.2 | length 5.3
  Top Layer (RF) w0.152: L22.2@90.45,26.868 L23.1@95.7,26.868
NetC81_2: C81.2 R28.1 R30.2 U8.7 | length 6.8
  Top Layer (RF) w0.152: U8.7@84.8,26.793 84.8,26.358 R28.1@86.65,24.508 R30.2@84.9,24.508 C81.2@84.9,22.508
NetC82_2: C82.2 R31.1 U8.5 | length 23.3
  Top Layer (RF) w0.152: v4(82.169,25.146) 82.169,22.352 83.185,21.336 87.884,21.336 89.691,23.143 R31.1@97.076,23.143
  Top Layer (RF) w0.2: C82.2@82.008,27.618 U8.5@83.525,27.618
  Int3 (Controls) w0.156: v1(81.986,27.609) 82.671,26.924 ; v4(82.169,25.146) 82.169,25.654 82.677,26.162 82.677,26.924
NetC83_1: C83.1 U9.1 | length 3.1
  Bottom Layer (RF) w0.143: U9.1@35.07,36.07 35.536,36.07 36.99,37.523 C83.1@37.556,37.523
NetC86_2: C86.2 U9.5 U9.6 | length 3.7
  Bottom Layer (RF) w0.143: U9.5@32.52,34.57 30.769,34.57 31.269,35.07 U9.6@32.52,35.07
NetC87_2: C87.2 U9.3 | length 1.9
  Bottom Layer (RF) w0.143: U9.3@35.07,35.07 35.745,35.07 36.358,34.457 36.358,34.371 C87.2@36.536,34.192
NetC90_2: C90.2 U10.3 | length 1.8
  Top Layer (RF) w0.2: C90.2@102.067,20.146 102.217,20.296 102.309,20.296 102.334,20.321 102.346,20.321 102.628,20.603 U10.3@103.674,20.603
NetC93_1: C93.1 L24.2 L25.1 | length 4
  Top Layer (RF) w0.152: L24.2@68.653,29.368 C93.1@70.653,29.368 L25.1@72.653,29.368
NetC94_1: C94.1 L25.2 R33.1 R34.1 | length 5.8
  Top Layer (RF) w0.152: L25.2@73.553,29.368 C94.1@75.553,29.368 R33.1@77.553,29.368 R34.1@79.303,29.368
NetC96_2: C96.2 L26.2 L27.1 | length 4
  Top Layer (RF) w0.152: L26.2@68.653,26.868 C96.2@70.653,26.868 L27.1@72.653,26.868
NetC97_2: C97.2 L27.2 R32.2 R35.1 | length 5.7
  Top Layer (RF) w0.152: L27.2@73.553,26.868 C97.2@75.553,26.868 R35.1@79.303,26.868
NetC100_1: C100.1 L28.2 L29.1 | length 4
  Top Layer (RF) w0.152: L28.2@68.653,60.25 C100.1@70.653,60.25 L29.1@72.653,60.25
NetC101_1: C101.1 L29.2 R37.1 R38.1 | length 5.8
  Top Layer (RF) w0.152: L29.2@73.553,60.25 C101.1@75.553,60.25 R38.1@79.303,60.25
NetC103_2: C103.2 L30.2 L31.1 | length 4
  Top Layer (RF) w0.152: L30.2@68.653,57.75 L31.1@72.653,57.75
NetC104_2: C104.2 L31.2 R36.2 R39.1 | length 5.8
  Top Layer (RF) w0.152: L31.2@73.553,57.75 R36.2@77.553,57.75 R39.1@79.303,57.75
NetC107_1: C107.1 L32.2 L33.1 | length 4
  Top Layer (RF) w0.152: L32.2@68.653,45.25 L33.1@72.653,45.25
NetC108_1: C108.1 L33.2 R41.1 R42.1 | length 5.8
  Top Layer (RF) w0.152: L33.2@73.553,45.25 C108.1@75.553,45.25 R41.1@77.553,45.25 R42.1@79.303,45.25
NetC110_2: C110.2 L34.2 L35.1 | length 4
  Top Layer (RF) w0.152: L34.2@68.653,42.75 C110.2@70.653,42.75 L35.1@72.653,42.75
NetC111_2: C111.2 L35.2 R40.2 R43.1 | length 5.8
  Top Layer (RF) w0.152: L35.2@73.553,42.75 C111.2@75.553,42.75 R43.1@79.303,42.75
NetC112_2: C112.2 R44.2 R46.1 U11.1 | length 6.8
  Top Layer (RF) w0.152: U11.1@84.8,12.844 84.8,13.329 R46.1@86.65,15.179 R44.2@84.9,15.179 C112.2@84.9,17.11
NetC113_1: C113.1 L36.2 L37.1 R48.1 | length 5.3
  Top Layer (RF) w0.152: L36.2@90.45,12.819 L37.1@95.7,12.819
NetC117_2: C117.2 L38.2 L39.1 R49.2 | length 5.3
  Top Layer (RF) w0.152: L38.2@90.45,10.319 R49.2@92.2,10.319 C117.2@93.95,10.319 L39.1@95.7,10.319
NetC119_2: C119.2 R53.1 R55.2 U11.7 | length 6.8
  Top Layer (RF) w0.133: C119.2@84.9,5.89 C119.2@84.9,5.959
  Top Layer (RF) w0.152: U11.7@84.8,10.244 84.8,9.809 R53.1@86.65,7.959 ; C119.2@84.9,5.959 R55.2@84.9,7.89
  Top Layer (RF) w0.156: R55.2@84.9,7.959 R53.1@86.65,7.959
NetC120_2: C120.2 R56.1 U11.5 | length 22.9
  Top Layer (RF) w0.152: v4(82.169,8.509) 82.169,6.35 83.693,4.826 87.953,4.826 89.696,6.57 R56.1@97.058,6.57
  Top Layer (RF) w0.2: C120.2@82.02,11.069 U11.5@83.525,11.069
  Int3 (Controls) w0.156: v1(81.957,11.023) 81.957,11.007 82.677,10.287 82.677,9.652 82.169,9.144 v4(82.169,8.509)
NetC121_2: C121.2 R57.2 R59.1 U12.1 | length 6.9
  Top Layer (RF) w0.152: U12.1@84.8,60.275 84.8,60.76 R59.1@86.65,62.61 R57.2@84.9,62.61 C121.2@84.9,64.61
NetC122_1: C122.1 L40.2 L41.1 R61.1 | length 5.3
  Top Layer (RF) w0.152: L40.2@90.45,60.25 L41.1@95.7,60.25
NetC126_2: C126.2 L42.2 L43.1 R62.2 | length 5.3
  Top Layer (RF) w0.152: L42.2@90.45,57.75 R62.2@92.2,57.75 C126.2@93.95,57.75 L43.1@95.7,57.75
NetC128_2: C128.2 R66.1 R68.2 U12.7 | length 6.8
  Top Layer (RF) w0.152: U12.7@84.8,57.675 84.8,57.24 R66.1@86.65,55.39 R68.2@84.9,55.39 C128.2@84.9,53.39
NetC129_2: C129.2 R69.1 U12.5 | length 22.7
  Top Layer (RF) w0.152: v1(82.169,55.88) 82.169,53.594 83.312,52.451 87.122,52.451 88.688,54.017 R69.1@97.176,54.017
  Top Layer (RF) w0.2: C129.2@82.223,58.5 U12.5@83.525,58.5
  Int3 (Controls) w0.15: v1(82.169,55.88) 82.169,56.515 82.677,57.023 82.677,57.912 v1(82.169,58.42)
NetC130_2: C130.2 R70.2 R72.1 U13.1 | length 6.9
  Top Layer (RF) w0.152: U13.1@84.8,45.275 84.8,45.76 R72.1@86.65,47.61 R70.2@84.9,47.61
  Top Layer (RF) w0.156: R70.2@84.9,47.61 C130.2@84.9,49.61
NetC131_1: C131.1 L44.2 L45.1 R74.1 | length 5.3
  Top Layer (RF) w0.152: L44.2@90.45,45.25 R74.1@92.2,45.25 C131.1@93.95,45.25 L45.1@95.7,45.25
NetC135_2: C135.2 L46.2 L47.1 R75.2 | length 5.3
  Top Layer (RF) w0.152: L46.2@90.45,42.75 L47.1@95.7,42.75
NetC137_2: C137.2 R79.1 R81.2 U13.7 | length 6.8
  Top Layer (RF) w0.152: U13.7@84.8,42.675 84.8,42.24 R79.1@86.65,40.39 R81.2@84.9,40.39 C137.2@84.9,38.39
NetC138_2: C138.2 R82.1 U13.5 | length 23.3
  Top Layer (RF) w0.152: v4(82.296,40.767) 82.296,37.846 83.312,36.83 87.122,36.83 89.26,38.968 R82.1@97.11,38.968
  Top Layer (RF) w0.2: C138.2@82.317,43.5 U13.5@83.525,43.5
  Int3 (Controls) w0.156: v1@82.23,43.408 82.804,42.834 82.804,42.037 82.296,41.529 v4(82.296,40.767)
  other v1: 82.22,43.408
NetC141_2: C141.2 U14.3 | length 1.9
  Top Layer (RF) w0.2: C141.2@102.186,3.514 103.002,4.33 U14.3@103.773,4.33
NetC144_2: C144.2 U15.3 | length 1.6
  Top Layer (RF) w0.2: C144.2@102.75,51.462 102.95,51.662 U15.3@104.301,51.662
NetC147_2: C147.2 U16.3 | length 1.9
  Top Layer (RF) w0.2: C147.2@101.988,35.823 102.138,35.973 102.245,35.973 102.767,36.495 U16.3@103.613,36.495
NetFB1_1: FB1.1 FB2.2 | length 1.5
  Top Layer (RF) w0.156: FB2.2@19.32,23.396 FB1.1@19.32,24.896
NetFB2_1: FB2.1 L16.1 U5.7 | length 3.5
  Top Layer (RF) w0.143: U5.7@17.32,22.496 FB2.1@19.32,22.496 L16.1@20.82,22.496
NetFB3_1: FB3.1 FB4.2 | length 1.5
  Top Layer (RF) w0.2: FB4.2@19.32,53.396 FB3.1@19.32,54.896
NetFB4_1: FB4.1 L19.1 U7.7 | length 3.5
  Top Layer (RF) w0.143: U7.7@17.32,52.496 FB4.1@19.32,52.496 19.499,52.496 L19.1@20.82,52.496
NetJ5_6: J5.2 U1.6 | length 17.7
  Top Layer (RF) w0.143: U1.6@116.795,35.466 116.795,35.101 116.821,35.076 116.821,23.679 118,22.5 119.25,22.5
  Top Layer (RF) w0.5: 119.25,22.5 J5.2@122.25,22.5
NetJ6_6: J6.2 U1.10 | length 19.8
  Top Layer (RF) w0.143: U1.10@116.795,37.466 116.795,51.295 118,52.5 119.25,52.5
  Top Layer (RF) w0.5: 119.25,52.5 J6.2@122.25,52.5
NetL15_2: L15.2 U5.2 | length 1.5
  Top Layer (RF) w0.143: L15.2@14.05,22.5 U5.2@15.55,22.5
NetL17_2: L17.2 T5.6 | length 2
  Top Layer (RF) w0.143: L17.2@29.52,22.496 T5.6@31.52,22.496
NetL18_2: L18.2 U7.2 | length 1.5
  Top Layer (RF) w0.143: L18.2@14.05,52.5 U7.2@15.55,52.5
NetL20_1: L20.1 R20.1 R21.2 | length 5.7
  Top Layer (RF) w0.152: R21.2@87.55,31.728 87.55,30.568 88.75,29.368 L20.1@89.55,29.368 R20.1@89.55,31.368
NetL22_1: L22.1 R27.1 R28.2 | length 5.7
  Top Layer (RF) w0.152: R28.2@87.55,24.508 87.55,25.668 88.75,26.868 L22.1@89.55,26.868 R27.1@89.55,24.868
NetL36_1: L36.1 R45.1 R46.2 | length 5.7
  Top Layer (RF) w0.152: R46.2@87.55,15.179 87.55,14.019 88.75,12.819 L36.1@89.55,12.819
  Top Layer (RF) w0.156: L36.1@89.55,12.819 R45.1@89.55,14.819
NetL38_1: L38.1 R52.1 R53.2 | length 5.7
  Top Layer (RF) w0.152: R53.2@87.55,7.959 87.55,9.119 88.75,10.319 L38.1@89.55,10.319 R52.1@89.55,8.319
NetL40_1: L40.1 R58.1 R59.2 | length 5.7
  Top Layer (RF) w0.152: R59.2@87.55,62.61 87.55,61.45 88.75,60.25 L40.1@89.55,60.25 R58.1@89.55,62.25
NetL42_1: L42.1 R65.1 R66.2 | length 5.7
  Top Layer (RF) w0.152: R66.2@87.55,55.39 87.55,56.55 88.75,57.75 L42.1@89.55,57.75 R65.1@89.55,55.75
NetL44_1: L44.1 R71.1 R72.2 | length 5.7
  Top Layer (RF) w0.152: R72.2@87.55,47.61 87.55,46.45 88.75,45.25 L44.1@89.55,45.25 R71.1@89.55,47.25
NetL46_1: L46.1 R78.1 R79.2 | length 5.7
  Top Layer (RF) w0.152: R79.2@87.55,40.39 87.55,41.55 88.75,42.75 L46.1@89.55,42.75 R78.1@89.55,40.75
NetR11_1: R11.1 U3.22 | length 2.2
  Bottom Layer (RF) w0.133: R11.1@48.496,30.824 48.496,32.149 48.745,32.398 U3.22@48.745,32.958
NetR20_2: R20.2 R22.1 R23.2 | length 6.2
  Top Layer (RF) w0.152: R20.2@90.45,31.368 91.1,31.368 R23.2@92.2,30.268 93.3,31.368 R22.1@95.7,31.368
NetR24_1: R24.1 R27.2 R29.1 | length 6.2
  Top Layer (RF) w0.152: R27.2@90.45,24.868 91.1,24.868 R24.1@92.2,25.968 93.3,24.868 R29.1@95.7,24.868
NetR45_2: R45.2 R47.1 R48.2 | length 6.2
  Top Layer (RF) w0.152: R45.2@90.45,14.819 91.1,14.819 R48.2@92.2,13.719 93.3,14.819 R47.1@95.7,14.819
NetR49_1: R49.1 R52.2 R54.1 | length 6.2
  Top Layer (RF) w0.152: R52.2@90.45,8.319 91.1,8.319 R49.1@92.2,9.419 93.3,8.319 R54.1@95.7,8.319
NetR58_2: R58.2 R60.1 R61.2 | length 6.2
  Top Layer (RF) w0.152: R58.2@90.45,62.25 91.1,62.25 R61.2@92.2,61.15 93.3,62.25 R60.1@95.7,62.25
NetR62_1: R62.1 R65.2 R67.1 | length 6.2
  Top Layer (RF) w0.152: R65.2@90.45,55.75 91.1,55.75 R62.1@92.2,56.85 93.3,55.75 R67.1@95.7,55.75
NetR71_2: R71.2 R73.1 R74.2 | length 6.2
  Top Layer (RF) w0.152: R71.2@90.45,47.25 91.1,47.25 R74.2@92.2,46.15 93.3,47.25 R73.1@95.7,47.25
NetR75_1: R75.1 R78.2 R80.1 | length 6.2
  Top Layer (RF) w0.152: R78.2@90.45,40.75 91.1,40.75 R75.1@92.2,41.85 93.3,40.75 R80.1@95.7,40.75
"Q HE CH": T4.1 U1.4 | length 14.7
  Top Layer (RF) w0.143: T4.1@104.34,45.27 104.36,45.25 106.25,45.25 108.639,42.861 108.639,37.361 110.034,35.966 U1.4@111.895,35.966 U1.4@111.817,36.044
"Q LE CH": T2.1 U1.7 | length 31.5
  Top Layer (RF) w0.143: U1.7@116.795,35.966 116.816,35.944 v1@117.72,35.944
  Top Layer (RF) w0.15: T2.1@104.34,12.839 105.839,12.839 113.646,20.646 113.646,31.896 115.195,33.445 v4(115.617,33.445)
  Int3 (Controls) w0.142: v4(115.617,33.445) 116.945,33.445 117.75,34.25 117.75,35.915 v1(117.742,35.923)
Q_HE_AA_N: L45.2 R73.2 R77.1 T4.6 | length 7.2
  Top Layer (RF) w0.152: L45.2@96.6,45.27 R73.2@96.6,47.25 ; L45.2@96.62,45.27 T4.6@101.16,45.27 ; R77.1@98.053,44.541 98.053,45.261
Q_HE_AA_P: L47.2 R76.1 R80.2 T4.4 | length 7.5
  Top Layer (RF) w0.152: R80.2@96.6,40.75 L47.2@96.6,42.73 ; L47.2@96.62,42.73 T4.4@101.16,42.73 ; R76.1@98.008,41.673 98.008,42.694
Q_HE_LPF_INPUT_N: C109.2 L34.1 U6.20 | length 45.7
  Top Layer (RF) w0.128: U6.20@29.946,55.182 29.946,55.672 31.754,57.479 34.479,57.479 35.342,56.617 47.029,56.617 59.838,43.809 65.192,43.809 65.742,43.809 65.819,43.731 C109.2@65.819,42.934
  Top Layer (RF) w0.133: U6.20@29.946,55.182 U6.20@30.005,55.123 ; C109.2@65.819,42.934 C109.2@66.003,42.75
  Top Layer (RF) w0.152: C109.2@66.003,42.75 L34.1@67.753,42.75
Q_HE_LPF_INPUT_P: C106.1 L32.1 U6.21 | length 46.3
  Top Layer (RF) w0.128: 29.564,55.484 29.564,55.83 31.596,57.862 34.638,57.862 35.5,57 47.188,57 59.997,44.191 65.351,44.191 65.742,44.191 65.819,44.269 C106.1@65.819,45.066
  Top Layer (RF) w0.133: U6.21@29.505,55.123 29.564,55.182 29.564,55.484 ; C106.1@65.819,45.066 C106.1@66.003,45.25
  Top Layer (RF) w0.152: C106.1@66.003,45.25 L32.1@67.753,45.25
Q_HE_LPF_OUTPUT_N: C137.1 R43.2 R81.1 U13.6 | length 8.8
  Top Layer (RF) w0.152: R43.2@80.203,42.75 81.453,41.5 82.5,41.5 ; C137.1@84,38.39 R81.1@84,40.39 83.61,40.39 82.5,41.5 ; U13.6@84,42.675 82.825,41.5 82.5,41.5
Q_HE_LPF_OUTPUT_P: C130.1 R42.2 R70.1 U13.2 | length 8.8
  Top Layer (RF) w0.152: R42.2@80.203,45.25 81.453,46.5 82.5,46.5 ; U13.2@84,45.325 82.825,46.5 82.5,46.5 ; R70.1@84,47.61 83.61,47.61 82.5,46.5
  Top Layer (RF) w0.156: R70.1@84,47.61 C130.1@84,49.61
Q_LE_AA_N: L37.2 R47.2 R51.1 T2.6 | length 7.3
  Top Layer (RF) w0.152: L37.2@96.6,12.839 R47.2@96.6,14.819 ; L37.2@96.62,12.839 T2.6@101.16,12.839 ; 97.98,12.838 R51.1@97.986,12.075
Q_LE_AA_P: L39.2 R50.1 R54.2 T2.4 | length 7.5
  Top Layer (RF) w0.152: R54.2@96.6,8.319 L39.2@96.6,10.299 ; L39.2@96.62,10.299 T2.4@101.16,10.299 ; R50.1@97.959,9.309 97.959,10.297
Q_LE_LPF_INPUT_N: C5.2 L3.1 U4.20 | length 38.6
  Top Layer (RF) w0.128: U4.20@43.731,24.059 43.67,24.12 43.67,25.67 45,27 48.407,27 50.169,25.238 59.228,25.238 63.2,21.265 63.2,12.8 64.62,11.38 65.742,11.38 65.817,11.305 65.817,10.505 C5.2@66.003,10.319
  Top Layer (RF) w0.152: C5.2@66.003,10.319 L3.1@67.753,10.319
Q_LE_LPF_INPUT_P: C2.1 L1.1 U4.21 | length 39.3
  Top Layer (RF) w0.128: U4.21@43.231,24.059 43.292,24.059 43.292,25.826 44.844,27.378 48.564,27.378 50.326,25.616 59.384,25.616 63.578,21.422 63.578,12.956 64.776,11.758 65.742,11.758 65.817,11.833 65.817,12.633 C2.1@66.003,12.819
  Top Layer (RF) w0.152: C2.1@66.003,12.819 L1.1@67.753,12.819
Q_LE_LPF_OUTPUT_N: C119.1 R4.2 R55.1 U11.6 | length 8.8
  Top Layer (RF) w0.152: R4.2@80.203,10.319 81.453,9.069 82.825,9.069 U11.6@84,10.244 ; 82.483,9.066 83.593,7.956 ; 83.609,7.959 R55.1@84,7.959 ; C119.1@84,5.89 R55.1@84,7.89
Q_LE_LPF_OUTPUT_P: C112.1 R3.2 R44.1 U11.2 | length 8.8
  Top Layer (RF) w0.152: R3.2@80.203,12.819 81.453,14.069 82.825,14.069 U11.2@84,12.894 ; 82.494,14.066 83.604,15.175 ; 83.609,15.179 R44.1@84,15.179 ; R44.1@84,15.11 C112.1@84,17.11
REFIN: C9.2 J7.6 | length 57
  Int3 (Controls) w0.142: v1(40.651,28.792) 40.65,45.4 66.31,71.06 J7.6@66.31,73.205 J7.6@65.832,72.727
  Bottom Layer (RF) w0.156: v1(40.651,28.792) 41.962,28.792 C9.2@41.978,28.809
RESET: J7.1 U2.14 | length 16.2
  Top Layer (RF) w0.2: U2.14@42.8,68.35 v1@42.8,70.448
  Int3 (Controls) w0.142: v1(42.806,70.428) 42.806,73.056 43.736,73.986 51.014,73.986 51.795,73.205 J7.1@53.61,73.205
SCK: J7.4 R14.2 U2.8 U3.1 | length 78.1
  Top Layer (RF) w0.2: U2.8@46.7,68.35 v1@46.7,71.494
  Int2 (5V+3.3V) w0.142: v1(46.518,41.13) 45.636,42.012 42.799,42.012 34.442,50.368 34.442,56.667 31.42,59.69 31.42,71.496 32.108,72.185 46.117,72.185 v1(46.71,71.592)
  Int3 (Controls) w0.142: v1(46.71,71.592) 48.576,69.725 57.75,69.725 J7.4@61.23,73.205
  Bottom Layer (RF) w0.156: v1(46.518,41.13) 47.745,39.903 U3.1@47.745,37.53
SW: R7.1 R8.1 U3.5 | length 28.5
  Int3 (Controls) w0.142: v1(49.756,38.605) 49.569,38.792 49.569,42.173 50.396,43 52,43 57,38 57,29.008 54.758,26.766 v1(54.307,26.766)
  Bottom Layer (RF) w0.1: U3.5@49.745,37.53 v1@49.745,38.594 ; R7.1@54.295,26.056 R7.1@54.307,26.067
  Bottom Layer (RF) w0.142: R7.1@54.307,26.067 v1(54.307,26.766) R8.1@54.307,27.394
VCC: C1.2 C50.2 C51.2 C52.1 C67.2 C69.2 C70.1 C76.1 C77.2 C78.2 C84.1 C89.1 C91.2 C98.2 C105.2 C114.1 C115.2 C116.2 C123.1 C124.2 C125.2 C132.1 C133.2 C134.2 C140.1 C143.1 C146.1 C150.2 FB1.2 FB3.2 J1.1 R1.1 R2.2 R32.1 R33.2 R36.1 R37.2 R40.1 R41.2 U1.8 U2.5 U4.10 U6.10 U8.4 U8.9 U9.7 U9.8 U10.6 U11.4 U11.9 U12.4 U12.9 U13.4 U13.9 U14.6 U15.6 U16.6 VCC.1 | length 106.2
  Top Layer (RF) w0.156: v1(18.409,27.289) C52.1@19.313,27.289 ; v4@29.505,46.888 U6.10@29.505,51.323 ; C51.2@43.231,17.057 U4.10@43.231,20.259 ; v4@43.271,15.911 C51.2@43.271,17.016 ; v1(80.974,12.049) 81.269,12.344 C115.2@81.924,12.344 ; v1(81.022,28.606) 81.321,28.905 C77.2@81.908,28.905 ; v1(81.081,44.486) 81.4,44.806 C133.2@81.936,44.806 ; v1(81.092,59.553) 81.093,59.555 81.9,59.555 82.007,59.661 C124.2@82.007,59.792 ; 86.868,59 86.868,59.763 C123.1@86.88,59.775 ; C125.2@86.87,58.159 86.87,58.998 ; 86.914,28.174 C76.1@86.914,28.953 ; C78.2@86.927,27.288 86.927,28.118 ; 86.934,44.001 C132.1@86.934,44.823 ; C134.2@86.937,43.269 86.937,43.942 ; C116.2@86.961,10.879 86.961,11.52 ; 86.961,11.596 C114.1@86.961,12.22 ; v1@88.666,28.118 v1(88.681,28.103) ; C146.1@106.828,37.528 C146.1@106.863,37.492
  Top Layer (RF) w0.2: v1(18.5,57.296) C70.1@19.32,57.296 ; FB1.2@19.32,25.796 C52.1@19.32,27.289 ; FB3.2@19.32,55.796 C70.1@19.32,57.296 ; U2.5@47.6,66.15 49.35,66.15 v1(49.75,65.75) ; v1(76.457,65.246) C98.2@77.496,65.246 ; v1(76.533,50.098) C105.2@77.517,50.098 ; v1(76.559,34.598) C91.2@77.526,34.598 ; v1(76.645,17.198) C1.2@77.545,17.198 ; v1(77.553,13.719) C1.2@77.553,17.191 ; v1(77.553,30.268) C91.2@77.553,34.571 ; v1(77.553,46.15) C105.2@77.553,50.063 ; v1(77.553,61.15) C98.2@77.553,65.189 ; C77.2@81.915,28.898 82.695,28.118 U8.4@83.525,28.118 ; C115.2@81.956,12.312 82.699,11.569 U11.4@83.525,11.569 ; C133.2@81.968,44.773 82.741,44 U13.4@83.525,44 ; C124.2@82.072,59.726 82.799,59 U12.4@83.525,59 ; U11.9@85.325,11.569 v1@87.999,11.569 ; U8.9@85.325,28.118 86.927,28.118 v1@88.666,28.118 ; U13.9@85.325,44 v1@87.885,44 ; U12.9@85.325,59 86.868,59 v1(87.622,59) ; U16.6@104.813,37.495 C146.1@106.795,37.495 ; U10.6@104.884,21.614 C89.1@106.72,21.614 ; U14.6@104.973,5.33 C140.1@106.829,5.33 ; U15.6@105.501,52.662 C143.1@107.441,52.662 ; C89.1@106.722,21.612 v1(107.804,21.612) ; C140.1@106.848,5.349 v4(107.952,5.349) ; C146.1@106.863,37.492 v1(107.999,37.492) ; C143.1@107.445,52.667 v1(108.318,52.667) ; U1.8@116.795,36.466 C150.2@118.963,36.466 ; C150.2@118.967,36.479 119.992,36.479 v1(120,36.487)
  Int3 (Controls) w0.142: v4(77.553,9.419) 78.169,9.419 78.5,9.75 78.5,12.772 v1(77.553,13.719) ; v4(77.553,56.85) 78.1,56.85 78.5,57.25 78.5,60.203 v1(77.553,61.15)
  Int3 (Controls) w0.156: v4(77.553,25.968) 78.218,25.968 78.5,26.25 78.5,29.321 v1(77.553,30.268) ; v4(77.553,41.85) 78.1,41.85 78.5,42.25 78.5,45.203 v1(77.553,46.15)
  Bottom Layer (RF) w0.142: C84.1@30.348,36.07 31,36.07 ; U9.7@32.52,35.57 31.5,35.57 31,36.07 ; U9.8@32.52,36.07 31,36.07
  Bottom Layer (RF) w0.156: v1(28.634,36.115) C84.1@30.303,36.115
  other v1: 88.011,11.557 87.894,44.009
  other v4: 43.256,15.824 29.512,46.878
VTUNE: C11.2 R5.2 U3.20 | length 7.5
  Bottom Layer (RF) w0.15: U3.20@49.745,32.958 49.745,32.328 49.562,32.145 49.562,29.114 50.37,28.306 C11.2@51.295,28.306 R5.2@52.795,28.306
pads on no net: C51.1 MH.MH U2.1 U2.2 U2.3 U2.4 U2.15 U2.16 U2.22 U2.23 U2.24 U2.25 U2.26 U2.27 U2.28 U3.25 U3.26 U4.1 U4.2 U4.3 U4.4 U4.11 U4.12 U4.24 U5.5 U6.1 U6.2 U6.3 U6.4 U6.11 U6.12 U6.24 U7.5 U8.3 U10.5 U11.3 U12.3 U13.3 U14.5 U15.5 U16.5

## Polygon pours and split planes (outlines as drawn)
VCC on Int2 (5V+3.3V) "VCC_L03_P029" (solid, pour order 29): 0,75 125,75 125,0 0,0
AVDD on Int2 (5V+3.3V) "AVDD_L03_P012" (solid, pour order 12): 34.75,41.248 34.75,32.7 41.014,32.764 41.062,28.1 43.6,28.1 45.677,28.1 45.677,26.1 48.5,26.1 50.1,26.1 50.1,24.5 53.3,24.5 55.75,24.5 55.761,24.489 56.633,24.489 56.633,19.58 56.633,18.887 58.169,18.887 58.169,24.469 58.2,24.5 58.2,38.1 57.6,38.7 54.4,38.7 54.4,41.9 53.7,42.6 52.1,42.6 52.1,46.5 49.2,49.4 47.4,49.4 46.8,50 45,50 45,56 44.338,56 41.5,56 41.5,47.998 41.5,41.2 37.4,41.2
GND on Int1 (GND) "GND_L02_P028" (solid, pour order 28): 0,75 125,75 125,0 0,0
GND on Int4 (GND) "GND_L05_P030" (solid, pour order 30): 0,75 125,75 125,0 0,0
GND on Top Layer (RF) "GND_L01_P031" (solid, pour order 31): 0,75 0,0 125,0 125,75
GND on Bottom Layer (RF) "GND_L06_P033" (solid, pour order 33): 0,75 125,75 125,0 0,0

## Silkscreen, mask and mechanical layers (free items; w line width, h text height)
Top Overlay:
  drawing of 9 lines, arcs and shapes, not listed
  text "QORVO_RADIO" at 103.09,72.651 h1.25
  text "GND" at 90.653,70.153 h1
  text "MUX_OUT" at 71.153,70.07 h1
  text "CS" at 64.347,69.403 h1 r90
  text "SCK" at 61.597,68.653 h1 r90
  text "CEN" at 69.419,68.403 h1 r90
  text "MOSI" at 59.347,67.653 h1 r90
  text "MISO" at 56.847,67.403 h1 r90
  text "REFIN" at 66.698,66.716 h1 r90
  text "RESET" at 54.097,66.403 h1 r90
  text "JLCJLCJLCJLC" at 21.537,65.459 h1 r45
